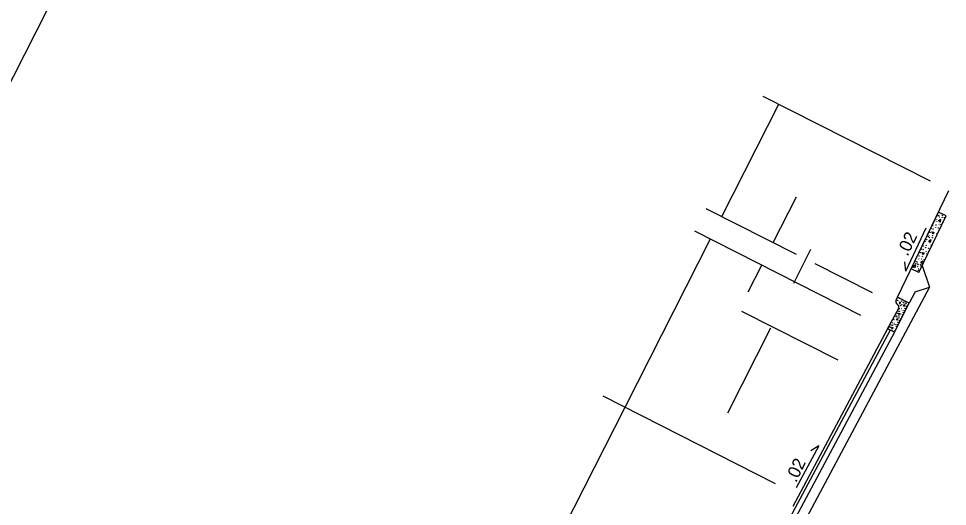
# Model space of a CAD drawing. Extents: x 1974386 to 1979988, y 776712 to 784860.
# Drawn here: x 1975892.7 to 1976335.5, y 780475.6 to 780708.3 of the extents above; entities that cross this region are included whole.
import ezdxf

# ---------------------------------------------------------------- set-up
doc = ezdxf.new("R2010")
doc.units = 0
for name, color, linetype in [('Default', 7, 'Continuous'), ('Old_Level_1', 7, 'Continuous'), ('Old_Level_2', 7, 'Continuous')]:
    doc.layers.add(name, color=color, linetype=linetype)

msp = doc.modelspace()

# ---------------------------------------------------------------- linework, layer by layer
at = {"layer": 'Default'}
msp.add_lwpolyline([(1978009.96, 784859.92), (1974385.88, 777715.09), (1976364.02, 776711.71), (1979988.11, 783856.54)], close=True, dxfattribs=at)
at = {"layer": 'Old_Level_1'}
for p, q in [((1976227.96, 780613.84), (1976255.1, 780667.36)), ((1976247.47, 780671.22), (1976327.22, 780630.79)), ((1976252.48, 780601.41), (1976263.56, 780623.27)), ((1976311.72, 780575.4), (1976336.22, 780626.22)), ((1976220.34, 780617.71), (1976263.37, 780595.89)), ((1976318.22, 780588.92), (1976331.23, 780615.96)), ((1976321.9, 780587.16), (1976334.9, 780614.2)), ((1976334.9, 780614.2), (1976331.23, 780615.96)), ((1976214.91, 780607.01), (1976294.12, 780566.84)), ((1976181.83, 780522.87), (1976222.53, 780603.14)), ((1976262.22, 780582.09), (1976270.44, 780598.31)), ((1976240.55, 780577.88), (1976247.05, 780590.71)), ((1976272.22, 780591.4), (1976299.55, 780577.54)), ((1976321.9, 780587.16), (1976318.22, 780588.92)), ((1976323.49, 780590.47), (1976326.89, 780580.1)), ((1976326.89, 780580.1), (1976253.72, 780442.69)), ((1976320.1, 780577.88), (1976326.89, 780580.1)), ((1976311.01, 780574.01), (1976311.72, 780575.4)), ((1976317.28, 780572.58), (1976311.72, 780575.4)), ((1976320.1, 780577.88), (1976317.28, 780572.58)), ((1976307, 780560.31), (1976312.23, 780569.85)), ((1976310.23, 780558.67), (1976317.28, 780572.58)), ((1976237.39, 780568.7), (1976283.27, 780545.44)), ((1976308.18, 780559.71), (1976216.39, 780387.73)), ((1976230.84, 780520.21), (1976251.37, 780560.69)), ((1976310.23, 780558.67), (1976249.59, 780444.79)), ((1976307, 780560.31), (1976261.87, 780475.56)), ((1976310.23, 780558.67), (1976307, 780560.31)), ((1976171.22, 780528.25), (1976253.42, 780486.57)), ((1976149.27, 780458.66), (1976181.83, 780522.87))]:
    msp.add_line(p, q, dxfattribs=at)
for centre, start, end in [((1976312.4, 780573.31), 153.1118, 240.3547), ((1976310.86, 780570.6), 331.2834, 60.3547)]:
    msp.add_arc(centre, 1.56, start, end, dxfattribs=at)
at = {"layer": 'Old_Level_2'}
for p, q in [((1976331.3, 780612.02), (1976332.27, 780612.55)), ((1976331.96, 780611.11), (1976331.3, 780612.02)), ((1976332.27, 780612.55), (1976331.96, 780611.11)), ((1976315.61, 780587.84), (1976325.35, 780608.37)), ((1976328.69, 780605.35), (1976328.08, 780606.46)), ((1976328.08, 780606.46), (1976329.09, 780606.3)), ((1976329.09, 780606.3), (1976328.69, 780605.35)), ((1976326.62, 780602.3), (1976327.59, 780602.82)), ((1976327.28, 780601.38), (1976326.62, 780602.3)), ((1976327.59, 780602.82), (1976327.28, 780601.38)), ((1976324.01, 780595.61), (1976323.41, 780596.73)), ((1976323.41, 780596.73), (1976324.42, 780596.58)), ((1976324.42, 780596.58), (1976324.01, 780595.61)), ((1976315.61, 780587.84), (1976315.25, 780592.29)), ((1976323.03, 780592.22), (1976324, 780592.74)), ((1976323.69, 780591.3), (1976323.03, 780592.22)), ((1976324, 780592.74), (1976323.69, 780591.3)), ((1976319.28, 780590.39), (1976320.25, 780590.91)), ((1976319.94, 780589.47), (1976319.28, 780590.39)), ((1976320.25, 780590.91), (1976319.94, 780589.47)), ((1976313.17, 780573.02), (1976312.51, 780572.32)), ((1976312.51, 780572.32), (1976313.04, 780572.17)), ((1976313.04, 780572.17), (1976313.17, 780573.02)), ((1976314.53, 780571.49), (1976315.21, 780571.84)), ((1976314.97, 780570.85), (1976314.53, 780571.49)), ((1976315.21, 780571.84), (1976314.97, 780570.85)), ((1976312.63, 780566.9), (1976312.22, 780567.68)), ((1976312.22, 780567.68), (1976312.92, 780567.56)), ((1976312.92, 780567.56), (1976312.63, 780566.9)), ((1976309.24, 780560.22), (1976308.84, 780561.01)), ((1976308.84, 780561.01), (1976309.54, 780560.89)), ((1976311.15, 780564.82), (1976311.83, 780565.17)), ((1976311.59, 780564.17), (1976311.15, 780564.82)), ((1976311.83, 780565.17), (1976311.59, 780564.17)), ((1976309.54, 780560.89), (1976309.24, 780560.22)), ((1976274.12, 780504.42), (1976263.42, 780484.38)), ((1976274.12, 780504.42), (1976270.34, 780502.06))]:
    msp.add_line(p, q, dxfattribs=at)
for centre, radius in [((1976331.01, 780614.03), 0.0693), ((1976331.48, 780614.34), 0.0693), ((1976333.03, 780614.36), 0.0693), ((1976328.25, 780609.88), 0.0693), ((1976329.44, 780611.77), 0.0693), ((1976330.06, 780609.78), 0.0693), ((1976330.28, 780612.52), 0.0693), ((1976330.44, 780611.44), 0.0693), ((1976331.53, 780610.03), 0.0693), ((1976331.7, 780613.53), 0.0693), ((1976332.41, 780610.01), 0.0693), ((1976333.02, 780613.44), 0.0693), ((1976333.37, 780611.2), 0.0693), ((1976333.97, 780613.26), 0.0693), ((1976327.26, 780606.36), 0.0693), ((1976327.69, 780608.02), 0.0693), ((1976328.58, 780609.56), 0.0693), ((1976328.59, 780607.86), 0.0693), ((1976329.81, 780608.7), 0.0693), ((1976330.43, 780605.66), 0.0693), ((1976331.14, 780608.38), 0.0693), ((1976331.38, 780607.17), 0.0693), ((1976324.76, 780602.05), 0.0693), ((1976325.6, 780602.79), 0.0693), ((1976326.33, 780604.3), 0.0693), ((1976326.8, 780604.61), 0.0693), ((1976327.02, 780603.81), 0.0693), ((1976328.35, 780604.64), 0.0693), ((1976328.34, 780603.72), 0.0693), ((1976328.69, 780601.47), 0.0693), ((1976322.58, 780596.63), 0.0693), ((1976323.01, 780598.29), 0.0693), ((1976323.57, 780600.15), 0.0693), ((1976323.9, 780599.83), 0.0693), ((1976323.91, 780598.13), 0.0693), ((1976325.13, 780598.97), 0.0693), ((1976325.36, 780597.22), 0.0693), ((1976325.38, 780600.05), 0.0693), ((1976326.46, 780598.66), 0.0693), ((1976326.7, 780597.45), 0.0693), ((1976327.73, 780600.29), 0.0693), ((1976320.88, 780592.27), 0.0693), ((1976321.86, 780593.62), 0.0693), ((1976321.95, 780594.95), 0.0693), ((1976322.79, 780591.9), 0.0693), ((1976323.01, 780593.5), 0.0693), ((1976323.67, 780594.91), 0.0693), ((1976324.46, 780593.3), 0.0693), ((1976325.75, 780595.93), 0.0693), ((1976319.04, 780590.06), 0.0693), ((1976319.16, 780589.4), 0.0693), ((1976320.12, 780589.54), 0.0693), ((1976320.38, 780591.46), 0.0693), ((1976321.22, 780589.89), 0.0693), ((1976321.28, 780591.74), 0.0693), ((1976321.47, 780590.88), 0.0693), ((1976321.6, 780588.17), 0.0693), ((1976321.62, 780588.88), 0.0693), ((1976322.74, 780590.87), 0.0693), ((1976322.89, 780590.25), 0.0693), ((1976312.66, 780574.66), 0.048), ((1976311.03, 780572.81), 0.048), ((1976311.76, 780571.75), 0.048), ((1976311.8, 780573.87), 0.048), ((1976312.39, 780570.05), 0.048), ((1976312.61, 780569.82), 0.048), ((1976312.64, 780573.1), 0.048), ((1976313.24, 780571.34), 0.048), ((1976313.57, 780573.51), 0.048), ((1976313.64, 780569.95), 0.048), ((1976313.83, 780571.84), 0.048), ((1976314.32, 780574), 0.048), ((1976314.36, 780572.88), 0.048), ((1976314.69, 780573.09), 0.048), ((1976314.83, 780572.53), 0.048), ((1976315.27, 780570.08), 0.048), ((1976315.75, 780572.44), 0.048), ((1976315.76, 780573.08), 0.048), ((1976315.95, 780570.88), 0.048), ((1976316.46, 780571.66), 0.048), ((1976317.15, 780572.72), 0.048), ((1976310.94, 780567.33), 0.048), ((1976310.98, 780566.21), 0.048), ((1976311.31, 780566.42), 0.048), ((1976311.45, 780565.86), 0.048), ((1976311.65, 780567.62), 0.048), ((1976311.97, 780568.76), 0.048), ((1976312.36, 780565.77), 0.048), ((1976312.38, 780566.41), 0.048), ((1976312.59, 780568.64), 0.048), ((1976313.45, 780569.2), 0.048), ((1976313.77, 780566.05), 0.048), ((1976313.84, 780567.09), 0.048), ((1976314.37, 780568.97), 0.048), ((1976314.51, 780568.13), 0.048), ((1976315.13, 780568.96), 0.048), ((1976307.85, 780561.47), 0.048), ((1976308.27, 780560.95), 0.048), ((1976308.59, 780562.09), 0.048), ((1976309.01, 780563.37), 0.048), ((1976309.21, 780561.97), 0.048), ((1976309.23, 780563.15), 0.048), ((1976309.85, 780564.67), 0.048), ((1976310.07, 780562.53), 0.048), ((1976310.26, 780563.28), 0.048), ((1976310.45, 780565.17), 0.048), ((1976310.98, 780562.3), 0.048), ((1976311.13, 780561.45), 0.048), ((1976311.75, 780562.29), 0.048), ((1976311.89, 780563.41), 0.048), ((1976312.57, 780564.21), 0.048), ((1976313.08, 780564.99), 0.048), ((1976307.55, 780560.66), 0.048), ((1976309, 780559.74), 0.048), ((1976310.39, 780559.38), 0.048), ((1976310.45, 780560.42), 0.048)]:
    msp.add_circle(centre, radius, dxfattribs=at)
msp.add_arc((1976311.23, 780568.14), 0.048, 233.9486, 67.4996, dxfattribs=at)

# ---------------------------------------------------------------- texts
for s, p in [('.02', (1976316.47, 780594.57)), ('.02 ', (1976263.35, 780486.62))]:
    msp.add_text(s, height=6, rotation=64.3034, dxfattribs=at).set_placement(p)

doc.saveas('drawing.dxf')
